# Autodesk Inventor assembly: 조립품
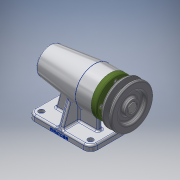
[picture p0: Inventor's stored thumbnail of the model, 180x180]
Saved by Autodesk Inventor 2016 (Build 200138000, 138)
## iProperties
Created: 2018-09
Part Number: 조립품
Document SubType Name: Assembly
Designer: CAMTIC
Author: CAMTIC
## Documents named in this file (12)
- C:\Users\CAMTIC\Desktop\480907V1023\답안조립품.iam
- C:\Users\CAMTIC\Desktop\480907V1023\본체.ipt
- C:\Users\CAMTIC\Desktop\480907V1023\베어링 51202.ipt
- C:\Users\CAMTIC\Desktop\480907V1023\어댑터슬리브.ipt
- C:\Users\CAMTIC\Desktop\480907V1023\베어링 6004.ipt
- C:\Users\CAMTIC\Desktop\480907V1023\축.ipt
- C:\Users\CAMTIC\Desktop\480907V1023\볼트 M4.ipt
- C:\Users\CAMTIC\Desktop\480907V1023\커버.ipt
- C:\Users\CAMTIC\Desktop\480907V1023\오일 실.ipt
- C:\Users\CAMTIC\Desktop\480907V1023\키 5 x 5 x 16.ipt
- C:\Users\CAMTIC\Desktop\480907V1023\V벨트풀리.ipt
- C:\Users\CAMTIC\Desktop\480907V1023\멈춤나사 M3.ipt
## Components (1 placed, 1 different names)
1. V벨트풀리:1
